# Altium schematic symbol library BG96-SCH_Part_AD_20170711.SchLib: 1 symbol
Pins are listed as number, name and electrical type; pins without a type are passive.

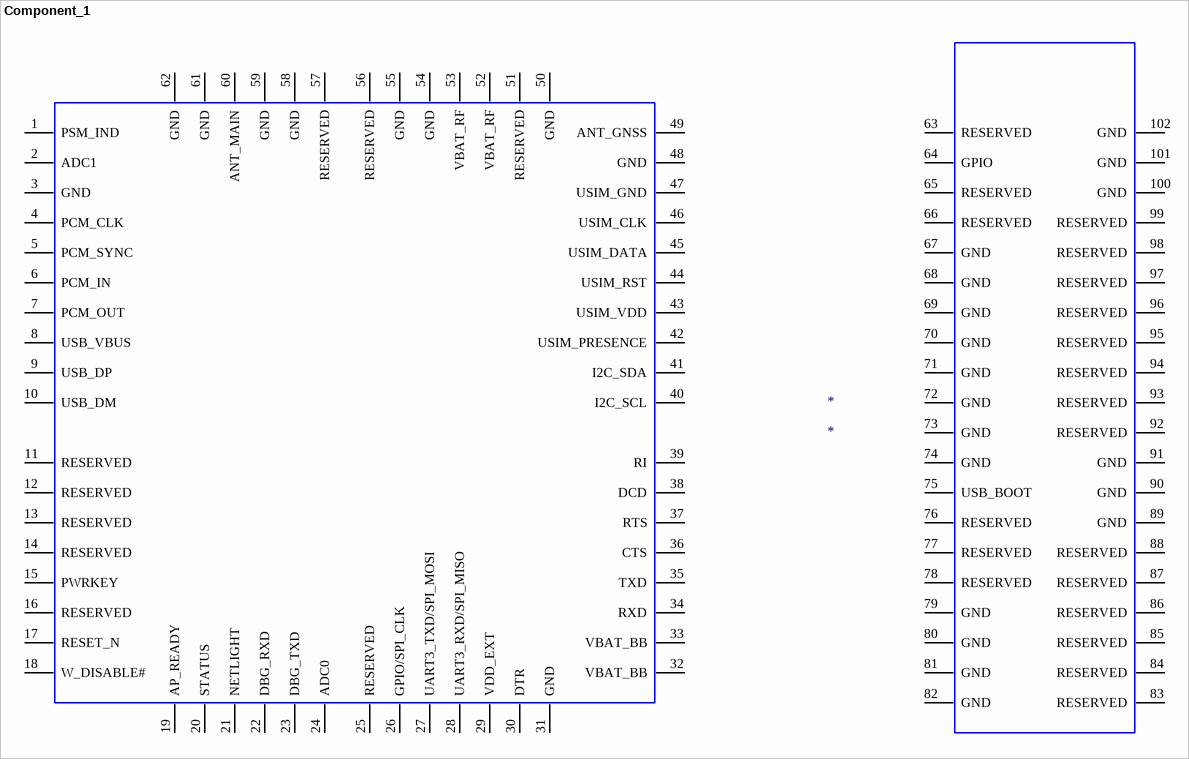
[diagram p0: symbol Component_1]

## Component_1
designator *
pins: 1 PSM_IND, 2 ADC1, 3 GND, 4 PCM_CLK, 5 PCM_SYNC, 6 PCM_IN, 7 PCM_OUT, 8 USB_VBUS, 9 USB_DP, 10 USB_DM, 11 RESERVED, 12 RESERVED, 13 RESERVED, 14 RESERVED, 15 PWRKEY, 16 RESERVED, 17 RESET_N, 18 W_DISABLE#, 19 AP_READY, 20 STATUS, 21 NETLIGHT, 22 DBG_RXD, 23 DBG_TXD, 24 ADC0, 25 RESERVED, 26 GPIO/SPI_CLK, 27 UART3_TXD/SPI_MOSI, 28 UART3_RXD/SPI_MISO, 29 VDD_EXT, 30 DTR, 31 GND, 32 VBAT_BB, 33 VBAT_BB, 34 RXD, 35 TXD, 36 CTS, 37 RTS, 38 DCD, 39 RI, 40 I2C_SCL, 41 I2C_SDA, 42 USIM_PRESENCE, 43 USIM_VDD, 44 USIM_RST, 45 USIM_DATA, 46 USIM_CLK, 47 USIM_GND, 48 GND, 49 ANT_GNSS, 50 GND, 51 RESERVED, 52 VBAT_RF, 53 VBAT_RF, 54 GND, 55 GND, 56 RESERVED, 57 RESERVED, 58 GND, 59 GND, 60 ANT_MAIN, 61 GND, 62 GND, 63 RESERVED, 64 GPIO, 65 RESERVED, 66 RESERVED, 67 GND, 68 GND, 69 GND, 70 GND, 71 GND, 72 GND, 73 GND, 74 GND, 75 USB_BOOT, 76 RESERVED, 77 RESERVED, 78 RESERVED, 79 GND, 80 GND, 81 GND, 82 GND, 83 RESERVED, 84 RESERVED, 85 RESERVED, 86 RESERVED, 87 RESERVED, 88 RESERVED, 89 GND, 90 GND, 91 GND, 92 RESERVED, 93 RESERVED, 94 RESERVED, 95 RESERVED, 96 RESERVED, 97 RESERVED, 98 RESERVED, 99 RESERVED, 100 GND, 101 GND, 102 GND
